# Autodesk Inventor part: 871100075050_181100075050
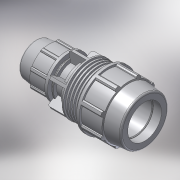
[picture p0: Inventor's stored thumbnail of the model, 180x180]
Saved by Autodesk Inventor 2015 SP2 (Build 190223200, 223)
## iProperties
Created: 2017-02
Part Number: 871100075050_181100075050
Material: PVC-Piping
Description: PLASSON REDUCING COUPLER 75-50
Document SubType Name: Modeling
Designer: KIM
Mass: 92.6774 g
Surface Area: 199.44 cm^2
Volume: 66.1981 cm^3
Density: 1.4 g/cm^3
Appearance: Smooth - White
Author: KIM
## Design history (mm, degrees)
derived "87110.ipt"
feature "Solid1::87110.ipt"
tag "TaggingFeature1"
body "Solid1"
other parameters: "d2" = 75, "d4" = 20.83333, "d5" = 35.71429, "d7" = 132, "d9" = 35.71429, "d11" = 3.57143, "d12" = 105.6, "d13" = 120 deg, "d14" = 105, "d15" = 6 deg, "d16" = 118.8, "d18" = 3.75, "d19" = 35 deg, "d20" = 17.5 deg, "d21" = 122.76, "d23" = 0, "d25" = 360 deg, "d27" = 2.64, "d42" = 55, "d46" = 1.5, "d52" = 35.71429, "d53" = 8 deg, "d54" = 137, "d58" = 67.5, "d59" = 45, "d60" = 86.4, "d61" = 76.8, "d62" = 31.25, "d63" = 45, "d64" = 120 deg, "d65" = 96, "d68" = 17.85714, "d74" = 89.28, "d75" = 35 deg, "d76" = 17.5 deg, "d78" = 0, "d80" = 360 deg, "d85" = 1.92, "d88" = 1, "d93" = 98, "d94" = 92.4, "d98" = 6.4, "d99" = 0, "d100" = 5.28, "d102" = 360 deg, "d104" = 2, "d106" = 0, "d107" = 6.4, "d108" = 0, "d109" = 6.4, "d110" = 0, "d111" = 3.31667, "d112" = 3.31667, "d113" = 3.31667, "d114" = 3.23571, "d116" = 3.23571, "d119" = 6.47143, "d125" = 116.424, "d_" = 75, "E_" = 132, "l_" = 137, "E_1" = 96, "l_1" = 98, "d96" = 9.95, "d115" = 32.35714
